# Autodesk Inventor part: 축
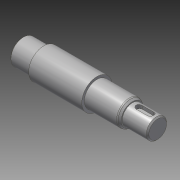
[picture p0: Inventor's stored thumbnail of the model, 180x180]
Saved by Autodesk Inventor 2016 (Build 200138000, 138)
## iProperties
Created: 2016-06
Part Number: 축
Material: 강철, 연강
Document SubType Name: Modeling
Designer: mduedu
Density: 7.86 g/cm^3
Appearance: 강철
Author: mduedu
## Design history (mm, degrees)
sketch "스케치1"
  geometry: L1 (-53.5, 0)-(53.5, 0); L2 (-53.5, 0)-(-53.5, 10); L3 (-53.5, 10)-(-36.5, 10); L4 (-36.5, 10)-(-36.5, 12); L5 (-36.5, 12)-(5.5, 12); L6 (5.5, 12)-(5.5, 10); L7 (5.5, 10)-(33.5, 10); L8 (33.5, 10)-(33.5, 8); L9 (33.5, 8)-(53.5, 8); L10 (53.5, 8)-(53.5, 0); 2 further points
  constraints: 20 end point, 5 parallel, 2 perpendicular, 1 coincident, 1 collinear, 1 horizontal, 1 midpoint, 1 vertical
  dimensions: "d0" = 107 distance of L1.start L1.end; "d2" = 16 diameter of L9 L1; "d3" = 20 diameter of L7 L1; "d4" = 24 diameter of L5 L1; "d5" = 20 diameter of L3 L1; "d6" = 17 distance of L2.end L3.end; "d7" = 20 distance of L8.end L9.end; "d8" = 48 distance from line of L5.end L10
revolve "회전1" sketch "스케치1" stored, may be unused: angle "d9" = 90 deg
chamfer "모따기1" distance "d10" = 2; stored, may be unused: second distance "d11" = 2, angle "d12" = 30 deg
fillet "모깎기1" dims "d13" = 2
node "작업 평면1"
sketch "스케치2"
  geometry: L1 (-4.5, 2.5)-(4.5, 2.5); L2 (4.5, -2.5)-(-4.5, -2.5); L3 (-4.5, 0)-(4.5, 0); L4 (-10, 8.845)-(-10, -8.845) reference; A1 r 2.5 centre (-4.5, 0) between (-4.5, 2.5) and (-4.5, -2.5); A2 r 2.5 centre (4.5, 0) between (4.5, -2.5) and (4.5, 2.5); 1 further point
  constraints: 6 end point, 4 point on circle, 3 tangent, 2 centre point, 2 parallel, 1 horizontal, 1 horizontal alignment
  dimensions: "d14" = 3 distance edge to line of A1 L4; "d15" = 5 distance between parallel lines of L2 L1; "d16" = 14 dimension on A2 A1
extrude "돌출1" cut sketch "스케치2" distance "d17" = 3; taper "d18" = 0 deg
chamfer "모따기2" distance "d19" = 1; stored, may be unused: second distance "d20" = 2, angle "d21" = 30 deg
sketch "스케치3"
  geometry: L1 (-33.5, -8)-(-52.5, -8) reference; L2 (-53.5, -7)-(-53.5, 7) reference; L3 (-36, -8)-(-37.5, -6.5); L4 (-37.5, -6.5)-(-37.5, -8); L5 (-36, -8)-(-37.5, -8); 1 further point
  constraints: 6 end point, 2 point on line, 1 collinear, 1 vertical
  dimensions: "d22" = 45 deg angle of L4 L3; "d23" = 16 distance between parallel lines of L2 L4; "d24" = 3 diameter of L3.start L4
revolve "회전2" stored, may be unused: angle "d25" = 90 deg
node "작업점1"
sketch "스케치4"
  geometry: 1 further point
hole "구멍1" sketch "스케치4" at (0, 0) diameter "d26" = 3.242; stored, may be unused: countersink angle "d30" = 90 deg, drill point angle "d32" = 120 deg; dims "d27" = 8, "d28" = 4, "d29" = 2, "d31" = 11
chamfer "모따기3" distance "d33" = 2; stored, may be unused: second distance "d34" = 2, angle "d35" = 30 deg
node "솔리드1"
